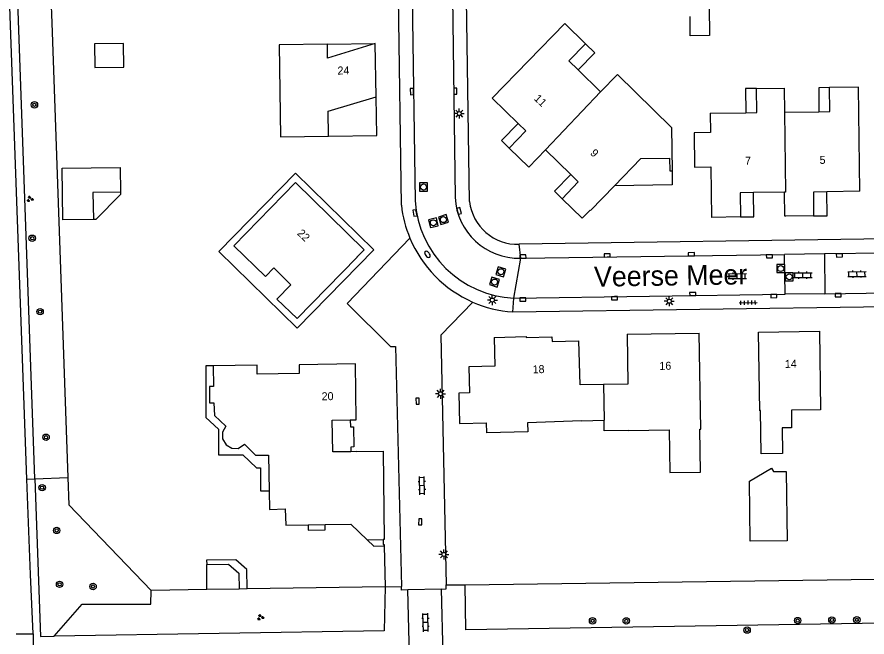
# Model space of a CAD drawing. Extents: x 128999 to 131010, y 395498 to 399007.
# Drawn here: x 130797.9 to 130904, y 395695.7 to 395773.2 of the extents above; entities that cross this region are included whole.
import ezdxf

# ---------------------------------------------------------------- set-up
doc = ezdxf.new("R2010")
doc.units = 0
for name, color, linetype in [('gg-afsc-erfafscheiding', 7, 'Continuous'), ('gg-afsc-hekwerk', 7, 'Continuous'), ('gg-afsc-muur', 7, 'Continuous'), ('gg-anno-huisnummerreeks BGT', 7, 'Continuous'), ('gg-anno-openbare ruimte label', 7, 'Continuous'), ('gg-bbg-bijgebouw', 7, 'Continuous'), ('gg-bbg-gedigitaliseerde bebouwing', 7, 'Continuous'), ('gg-bbg-gedigitaliseerde bijgebouw', 7, 'Continuous'), ('gg-bbg-hoofdgebouw', 7, 'Continuous'), ('gg-bbg-luifel en loopbrug', 7, 'Continuous'), ('gg-bbg-onder overbouw', 7, 'Continuous'), ('gg-bbg-pand overbouw', 7, 'Continuous'), ('gg-bbg-tussenscheiding', 7, 'Continuous'), ('gg-knt-verharding', 7, 'Continuous'), ('gt-grn-groengrens', 7, 'Continuous'), ('gt-grn-vlakafsluiter', 7, 'Continuous'), ('gt-grn-weggrens', 7, 'Continuous'), ('gt-symb-boom', 7, 'Continuous'), ('gt-symb-brandkraan', 7, 'Continuous'), ('gt-symb-groenvak', 7, 'Continuous'), ('gt-symb-klinker verharding', 7, 'Continuous'), ('gt-symb-kolk', 7, 'Continuous'), ('gt-symb-lichtmast', 7, 'Continuous'), ('gt-symb-rioolschacht', 7, 'Continuous'), ('gt-symb-tegel verharding', 7, 'Continuous')]:
    doc.layers.add(name, color=color, linetype=linetype)

# ---------------------------------------------------------------- blocks, each defined once
blk = doc.blocks.new('gt0-RS')
at = {"layer": 'gt-symb-rioolschacht'}
blk.add_lwpolyline([(-0.5, -0.5), (0.5, -0.5), (0.5, 0.5), (-0.5, 0.5)], close=True, dxfattribs=at)
blk.add_circle((0, 0), 0.375, dxfattribs=at)
blk = doc.blocks.new('gt0-KOLK')
at = {"layer": 'gt-symb-kolk'}
blk.add_lwpolyline([(0, 0), (0.38, 0), (0.38, 0.4), (-0.38, 0.4), (-0.38, 0), (0, 0)], dxfattribs=at)
blk = doc.blocks.new('gt0-KL1')
at = {"layer": 'gt-symb-klinker verharding'}
for p, q in [((-1.15, 0.3), (1.15, 0.3)), ((-1, -0.3), (-1, 0.3)), ((-0.5, 0.3), (-0.5, 0.45)), ((0, -0.3), (0, 0.3)), ((0.5, 0.3), (0.5, 0.45)), ((1, -0.3), (1, 0.3)), ((-1.15, -0.3), (1.15, -0.3)), ((-0.5, -0.45), (-0.5, -0.3)), ((0.5, -0.45), (0.5, -0.3))]:
    blk.add_line(p, q, dxfattribs=at)
blk = doc.blocks.new('gt0-BR')
at = {"layer": 'gt-symb-brandkraan'}
for centre, radius, start, end in [((-0.24, 0), 0.206, 107.5669, 252.4331), ((0.6, -2.66), 3, 106.892, 107.5669), ((0, -0.69), 0.938, 73.108, 106.892), ((-0.6, -2.66), 3, 72.4331, 73.108), ((0.24, 0), 0.206, 287.567, 72.4331), ((0.6, 2.66), 3, 252.4331, 253.108), ((0, 0.69), 0.938, 253.108, 286.8921), ((-0.6, 2.66), 3, 286.8921, 287.567)]:
    blk.add_arc(centre, radius, start, end, dxfattribs=at)
blk = doc.blocks.new('gt0-LMAST')
at = {"layer": 'gt-symb-lichtmast'}
for p, q in [((-0.18, 0.17), (-0.45, 0.44)), ((-0.01, 0.25), (-0.01, 0.62)), ((0.17, 0.17), (0.44, 0.44)), ((-0.26, 0), (-0.63, 0)), ((-0.18, -0.18), (-0.45, -0.45)), ((-0.01, -0.25), (-0.01, -0.63)), ((0.44, -0.45), (0.17, -0.18)), ((0.24, 0), (0.62, 0))]:
    blk.add_line(p, q, dxfattribs=at)
blk.add_circle((-0.01, 0), 0.25, dxfattribs=at)
blk = doc.blocks.new('gt0-TEG1')
at = {"layer": 'gt-symb-tegel verharding'}
for p, q in [((-1.12, 0), (1.12, 0)), ((-0.9, -0.25), (-0.9, 0.25)), ((-0.45, -0.25), (-0.45, 0.25)), ((0, -0.25), (0, 0.25)), ((0.45, -0.25), (0.45, 0.25)), ((0.9, -0.25), (0.9, 0.25))]:
    blk.add_line(p, q, dxfattribs=at)
blk = doc.blocks.new('gt0-BOOM')
at = {"layer": 'gt-symb-boom'}
for radius in [0.4, 0.2]:
    blk.add_circle((0, 0), radius, dxfattribs=at)
blk = doc.blocks.new('gt0-GRVAK')
at = {"layer": 'gt-symb-groenvak'}
for p, q in [((-0.11, 0.19), (-0.23, 0.24)), ((-0.18, 0.15), (0.09, 0.15)), ((-0.09, 0.21), (-0.16, 0.32)), ((-0.05, 0.21), (-0.05, 0.39)), ((0, 0.21), (0.06, 0.32)), ((0.01, 0.19), (0.13, 0.24)), ((0.26, -0.05), (0.2, 0.06)), ((0.31, -0.05), (0.31, 0.13)), ((0.35, -0.05), (0.41, 0.06)), ((-0.24, -0.23), (-0.36, -0.18)), ((-0.32, -0.26), (-0.05, -0.26)), ((-0.23, -0.21), (-0.29, -0.1)), ((-0.18, -0.2), (-0.18, -0.02)), ((-0.14, -0.21), (-0.07, -0.1)), ((-0.12, -0.23), (0, -0.18)), ((0.24, -0.07), (0.12, -0.02)), ((0.17, -0.11), (0.44, -0.11)), ((0.37, -0.07), (0.49, -0.02))]:
    blk.add_line(p, q, dxfattribs=at)

msp = doc.modelspace()

# ---------------------------------------------------------------- linework, layer by layer
at = {"layer": 'gg-afsc-erfafscheiding'}
for p, q in [((130802.21, 395772.43), (130804.21, 395715.6)), ((130804.21, 395715.6), (130804.33, 395712.2)), ((130814.6, 395701.51), (130804.33, 395712.2)), ((130821.58, 395701.61), (130814.6, 395701.51))]:
    msp.add_line(p, q, dxfattribs=at)
at = {"layer": 'gg-afsc-hekwerk'}
msp.add_line((130800.51, 395824.79), (130802.21, 395772.43), dxfattribs=at)
at = {"layer": 'gg-afsc-muur'}
for p, q in [((130843.72, 395707.06), (130843.84, 395701.97)), ((130843.84, 395701.97), (130826.59, 395701.69))]:
    msp.add_line(p, q, dxfattribs=at)
at = {"layer": 'gg-bbg-bijgebouw'}
for p, q in [((130821.58, 395701.61), (130821.55, 395704.73)), ((130825.59, 395701.67), (130821.58, 395701.61))]:
    msp.add_line(p, q, dxfattribs=at)
at = {"layer": 'gg-bbg-gedigitaliseerde bebouwing'}
for p, q in [((130857.22, 395762.99), (130866.28, 395772.32)), ((130866.28, 395772.32), (130868.86, 395769.81)), ((130867.93, 395766.55), (130870.75, 395763.81)), ((130884.42, 395761.13), (130888.89, 395761.19)), ((130884.42, 395761.13), (130884.45, 395758.72)), ((130893.72, 395761.27), (130898.01, 395761.32)), ((130863.85, 395756.54), (130861.79, 395754.37)), ((130884.51, 395754.41), (130884.59, 395748.11)), ((130833.1, 395729.71), (130833.1, 395728.59)), ((130868.35, 395722.71), (130871.18, 395722.76)), ((130831.42, 395709.67), (130834.21, 395709.71)), ((130834.21, 395709.71), (130836.33, 395709.75)), ((130841.59, 395707.83), (130843.6, 395707.86))]:
    msp.add_line(p, q, dxfattribs=at)
for points in [[(130836.62, 395769.76), (130830.59, 395769.68), (130830.78, 395758.18), (130836.78, 395758.26)], [(130868.86, 395769.81), (130866.78, 395767.66), (130867.93, 395766.55)], [(130870.75, 395763.81), (130872.84, 395765.96), (130879.59, 395759.36), (130879.67, 395753.95)], [(130888.89, 395761.19), (130890.26, 395761.21), (130890.22, 395764.21)], [(130890.22, 395764.21), (130893.68, 395764.26), (130893.72, 395761.27)], [(130898.01, 395761.32), (130899.38, 395761.34), (130899.35, 395764.33)], [(130903.13, 395751.39), (130902.94, 395764.37), (130899.35, 395764.33)], [(130884.45, 395758.72), (130882.43, 395758.69), (130882.48, 395754.38), (130884.51, 395754.41)], [(130832.65, 395752.46), (130824.95, 395744.57), (130828.89, 395740.73)], [(130828.89, 395740.73), (130829.92, 395741.79), (130832.07, 395739.69), (130830.33, 395737.91)], [(130874.24, 395721.5), (130879.29, 395721.58), (130879.38, 395716.24), (130883.21, 395716.3), (130883.14, 395721.65), (130883.25, 395721.65), (130883.07, 395733.64)], [(130898.07, 395733.88), (130898.21, 395724.08), (130894.57, 395724.01), (130894.6, 395721.82), (130893.41, 395721.8), (130893.47, 395718.61), (130890.78, 395718.57), (130890.71, 395723.97), (130890.61, 395723.96), (130890.47, 395733.76)], [(130822.35, 395729.57), (130822.41, 395726.98), (130821.9, 395726.97), (130821.89, 395724.94), (130822.45, 395724.96), (130822.52, 395723.35), (130823.93, 395722.02), (130823.51, 395721.27), (130823.54, 395720.44), (130823.97, 395719.71), (130824.7, 395719.3), (130825.5, 395719.25), (130826.26, 395719.76), (130827.65, 395718.4), (130829.27, 395718.42), (130829.34, 395713.94)], [(130833.1, 395728.59), (130827.85, 395728.51), (130827.84, 395729.65), (130822.35, 395729.57)], [(130868.35, 395722.71), (130861.63, 395722.44), (130861.66, 395721.31)], [(130874.24, 395721.5), (130871.2, 395721.45), (130871.18, 395722.76)], [(130829.34, 395713.94), (130829.38, 395711.63), (130831.37, 395711.68), (130831.42, 395709.67)], [(130836.33, 395709.75), (130839.56, 395709.8), (130841.59, 395707.83)]]:
    msp.add_lwpolyline(points, dxfattribs=at)
at = {"layer": 'gg-bbg-gedigitaliseerde bijgebouw'}
for points in [[(130807.54, 395769.79), (130807.59, 395766.85), (130811.21, 395766.9), (130811.16, 395769.85), (130807.54, 395769.79)], [(130803.5, 395754.25), (130810.74, 395754.36), (130810.79, 395751.28)], [(130807.4, 395747.85), (130803.6, 395747.79), (130803.5, 395754.25)], [(130810.79, 395751.28), (130807.35, 395751.23), (130807.4, 395747.85)], [(130892.07, 395716.78), (130892.32, 395716.35), (130893.92, 395716.38), (130894.04, 395707.71), (130889.44, 395707.65), (130889.34, 395715.14), (130892.07, 395716.78)], [(130821.55, 395704.73), (130824.26, 395704.8), (130825.56, 395703.67), (130825.59, 395701.67)]]:
    msp.add_lwpolyline(points, dxfattribs=at)
at = {"layer": 'gg-bbg-hoofdgebouw'}
for p, q in [((130842.71, 395763.19), (130842.61, 395769.85)), ((130860.46, 395759.84), (130857.22, 395762.99)), ((130861.79, 395754.37), (130859.31, 395756.77)), ((130867.02, 395753.47), (130863.85, 395756.54)), ((130893.71, 395751.25), (130889.83, 395751.21)), ((130903.13, 395751.39), (130898.98, 395751.3)), ((130888.2, 395748.18), (130884.59, 395748.11)), ((130897.35, 395748.29), (130893.89, 395748.25)), ((130830.33, 395737.91), (130832.84, 395735.46)), ((130874.07, 395733.51), (130883.07, 395733.64)), ((130890.47, 395733.76), (130898.07, 395733.88)), ((130857.45, 395733.1), (130857.54, 395729.51)), ((130840.12, 395729.82), (130833.1, 395729.71)), ((130840.29, 395718.85), (130839.56, 395718.84))]:
    msp.add_line(p, q, dxfattribs=at)
for points in [[(130836.78, 395758.26), (130836.74, 395761.38), (130842.71, 395763.19)], [(130859.31, 395756.77), (130861.4, 395758.92), (130860.46, 395759.84)], [(130872.47, 395752.06), (130875.78, 395755.46), (130879.35, 395755.51), (130879.38, 395753.94), (130879.67, 395753.95)], [(130865.93, 395750.45), (130867.96, 395752.55), (130867.02, 395753.47)], [(130832.65, 395752.46), (130841.23, 395744.08), (130840.3, 395743.13), (130840.31, 395743.11), (130832.84, 395735.46)], [(130865.93, 395750.45), (130868.44, 395748.01), (130869.44, 395749.03), (130869.49, 395748.99), (130872.47, 395752.06)], [(130889.83, 395751.21), (130888.16, 395751.19), (130888.2, 395748.18)], [(130893.89, 395748.25), (130893.74, 395748.25), (130893.71, 395751.25)], [(130898.98, 395751.3), (130897.32, 395751.27), (130897.35, 395748.29)], [(130857.45, 395733.1), (130861.44, 395733.23), (130861.45, 395733.09), (130864.67, 395733.2), (130864.69, 395732.6), (130868.01, 395732.71)], [(130874.07, 395733.51), (130874.16, 395727.27), (130871.12, 395727.23)], [(130871.12, 395727.23), (130868.2, 395727.2), (130868.01, 395732.71)], [(130839.48, 395722.82), (130840.23, 395722.83), (130840.12, 395729.82)], [(130857.54, 395729.51), (130854.29, 395729.44), (130854.37, 395726.19), (130853.03, 395726.16)], [(130853.03, 395726.16), (130853.12, 395722.35), (130856.51, 395722.43)], [(130839.56, 395718.84), (130837.29, 395718.81), (130837.23, 395722.79), (130839.48, 395722.82)], [(130861.66, 395721.31), (130856.54, 395721.18), (130856.51, 395722.43)], [(130840.29, 395718.85), (130843.57, 395718.9), (130843.7, 395707.86), (130843.6, 395707.86)]]:
    msp.add_lwpolyline(points, dxfattribs=at)
at = {"layer": 'gg-bbg-luifel en loopbrug'}
msp.add_line((130826.59, 395701.69), (130825.59, 395701.67), dxfattribs=at)
for points in [[(130884.3, 395774.47), (130884.34, 395770.82), (130881.94, 395770.79), (130881.91, 395773.23)], [(130868.86, 395769.81), (130870.01, 395768.69), (130867.93, 395766.55)], [(130890.22, 395764.21), (130888.85, 395764.2), (130888.89, 395761.19)], [(130899.35, 395764.33), (130897.98, 395764.31), (130898.01, 395761.32)], [(130836.78, 395758.26), (130842.78, 395758.35), (130842.71, 395763.19)], [(130859.31, 395756.77), (130858.37, 395757.7), (130860.46, 395759.84)], [(130823.06, 395743.85), (130832.84, 395734.29), (130842.41, 395744.08), (130832.63, 395753.64), (130823.06, 395743.85)], [(130865.93, 395750.45), (130864.98, 395751.38), (130867.02, 395753.47)], [(130879.67, 395753.95), (130879.7, 395752.17), (130872.47, 395752.06)], [(130810.79, 395751.28), (130810.79, 395750.98), (130807.7, 395747.86), (130807.4, 395747.85)], [(130888.2, 395748.18), (130889.86, 395748.2), (130889.83, 395751.21)], [(130897.35, 395748.29), (130899.02, 395748.31), (130898.98, 395751.3)], [(130822.35, 395729.57), (130821.46, 395729.57), (130821.46, 395723.13), (130823.04, 395721.64), (130823.04, 395718.45), (130826.05, 395718.45), (130827.77, 395716.82), (130828.27, 395716.82), (130828.27, 395713.94), (130829.34, 395713.94)], [(130839.48, 395722.82), (130839.5, 395721.93), (130839.9, 395721.93), (130839.94, 395719.43), (130839.55, 395719.42), (130839.56, 395718.84)], [(130834.21, 395709.71), (130834.22, 395709.04), (130836.34, 395709.07), (130836.33, 395709.75)], [(130841.59, 395707.83), (130842.41, 395707.05), (130843.72, 395707.06)], [(130843.6, 395707.86), (130843.61, 395707.25), (130843.71, 395707.25), (130843.72, 395707.06)], [(130826.59, 395701.69), (130826.55, 395704.14), (130825.18, 395705.32), (130821.54, 395705.27), (130821.55, 395704.73)]]:
    msp.add_lwpolyline(points, dxfattribs=at)
at = {"layer": 'gg-bbg-onder overbouw'}
msp.add_lwpolyline([(130842.61, 395769.85), (130836.64, 395768.02), (130836.62, 395769.76)], dxfattribs=at)
at = {"layer": 'gg-bbg-pand overbouw'}
msp.add_line((130836.62, 395769.76), (130842.61, 395769.85), dxfattribs=at)
at = {"layer": 'gg-bbg-tussenscheiding'}
for p, q in [((130870.75, 395763.81), (130863.85, 395756.54)), ((130871.12, 395727.23), (130871.18, 395722.76))]:
    msp.add_line(p, q, dxfattribs=at)
msp.add_lwpolyline([(130893.72, 395761.27), (130893.85, 395751.25), (130893.71, 395751.25)], dxfattribs=at)
at = {"layer": 'gg-knt-verharding'}
for p, q in [((130799.11, 395715.42), (130792.95, 395886.49)), ((130852, 395793.69), (130852.58, 395750.61)), ((130846.96, 395793.53), (130847.57, 395750.19)), ((130928.3, 395745.77), (130860.57, 395744.75)), ((130927.72, 395743.93), (130898.71, 395743.54)), ((130860.77, 395743.03), (130893.73, 395743.47)), ((130898.71, 395743.54), (130893.73, 395743.47)), ((130893.81, 395738.5), (130893.73, 395743.47)), ((130898.71, 395743.54), (130898.73, 395738.57)), ((130859.91, 395738.03), (130893.81, 395738.5)), ((130898.73, 395738.57), (130893.81, 395738.5)), ((130898.73, 395738.57), (130927.16, 395738.97)), ((130926.92, 395737.24), (130859.78, 395736.29)), ((130799.54, 395703.48), (130799.11, 395715.42)), ((130799.88, 395696.09), (130799.54, 395703.48)), ((130850.88, 395701.68), (130846.66, 395701.56)), ((130846.88, 395693.37), (130846.66, 395701.56)), ((130851.1, 395693.41), (130850.88, 395701.68)), ((130797.75, 395696.09), (130799.88, 395696.09)), ((130799.88, 395696.09), (130799.95, 395692.82))]:
    msp.add_line(p, q, dxfattribs=at)
for points in [[(130845.87, 395749.62), (130845.12, 395801.5), (130844.38, 395857.63)], [(130854.38, 395750.1), (130853.62, 395800.73), (130852.88, 395857.84)], [(130846.94, 395745.52), (130839.1, 395737.36), (130844.52, 395731.97), (130845.11, 395731.97), (130845.88, 395702)], [(130854.77, 395737.54), (130850.8, 395733.38), (130851.46, 395702.19)], [(130846.66, 395701.56), (130845.89, 395701.54), (130845.88, 395702)], [(130850.88, 395701.68), (130851.47, 395701.69), (130851.46, 395702.19)]]:
    msp.add_lwpolyline(points, dxfattribs=at)
for centre, radius, start, end in [((130860.53, 395751), 12.99, 183.5836, 267.286), ((130860.51, 395750.96), 7.94, 182.5215, 271.848), ((130860.83, 395751.33), 15.06, 186.5107, 202.6833), ((130860.38, 395750.79), 6.04, 186.5526, 271.771), ((130860.84, 395751.33), 15.07, 202.6742, 246.2171), ((130860.84, 395751.33), 15.07, 246.2162, 265.9321)]:
    msp.add_arc(centre, radius, start, end, dxfattribs=at)
at = {"layer": 'gt-grn-groengrens'}
for p, q in [((130799.11, 395715.42), (130800.1, 395715.45)), ((130800.1, 395715.45), (130804.21, 395715.6))]:
    msp.add_line(p, q, dxfattribs=at)
for points in [[(130800.1, 395715.45), (130793.95, 395886.12), (130793.99, 395888.96), (130794.71, 395892.91), (130796.85, 395897.52), (130799.92, 395901.1), (130803.59, 395902.78), (130807.67, 395902.98)], [(130800.1, 395715.45), (130800.8, 395695.75), (130802.49, 395695.81)], [(130843.84, 395701.97), (130843.73, 395696.44), (130802.49, 395695.81)], [(130802.49, 395695.81), (130806.01, 395699.79), (130814.57, 395699.79), (130814.6, 395701.51)], [(130986.77, 395698.72), (130853.93, 395696.6), (130853.81, 395702.22)]]:
    msp.add_lwpolyline(points, dxfattribs=at)
at = {"layer": 'gt-grn-vlakafsluiter'}
for p, q in [((130843.84, 395701.97), (130845.88, 395702)), ((130851.46, 395702.19), (130853.81, 395702.22))]:
    msp.add_line(p, q, dxfattribs=at)
msp.add_lwpolyline([(130853.81, 395702.22), (130980.39, 395703.95), (130986.9, 395718.19)], dxfattribs=at)
at = {"layer": 'gt-grn-weggrens'}
for p, q in [((130860.77, 395743.03), (130860.57, 395744.75)), ((130859.91, 395738.03), (130860.77, 395743.03)), ((130859.78, 395736.29), (130859.91, 395738.03))]:
    msp.add_line(p, q, dxfattribs=at)

# ---------------------------------------------------------------- block references
at = {"layer": 'gt-symb-boom'}
for p in [(130800.04, 395762.18), (130799.76, 395745.51), (130800.75, 395736.34), (130801.49, 395720.65), (130801, 395714.34), (130802.82, 395709), (130803.18, 395702.27), (130807.36, 395702), (130895.36, 395697.74), (130899.63, 395697.81), (130902.74, 395697.83), (130869.74, 395697.71), (130873.95, 395697.7), (130889.04, 395696.55)]:
    msp.add_blockref('gt0-BOOM', p, dxfattribs=at)
at = {"layer": 'gt-symb-brandkraan', "rotation": 128.50778297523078}
msp.add_blockref('gt0-BR', (130849.12, 395743.5), dxfattribs=at)
at = {"layer": 'gt-symb-groenvak'}
for p in [(130799.48, 395750.4), (130828.26, 395698.15)]:
    msp.add_blockref('gt0-GRVAK', p, dxfattribs=at)
at = {"layer": 'gt-symb-klinker verharding'}
for p, rotation in [((130887.8, 395740.78), 0.8020885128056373), ((130896.01, 395740.89), -0.11459140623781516), ((130902.76, 395741.03), 0.8593722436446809), ((130848.44, 395714.59), 91.0884888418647), ((130848.88, 395697.5), 91.5466102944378)]:
    msp.add_blockref('gt0-KL1', p, dxfattribs=dict(at, rotation=rotation))
at = {"layer": 'gt-symb-kolk'}
for p, rotation in [((130847.38, 395763.83), 90.74480317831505), ((130852.4, 395763.88), -89.25519682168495), ((130847.75, 395748.7), 100.5457343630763), ((130852.87, 395748.87), -75.10181274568), ((130861.05, 395743.03), 0.40106390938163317), ((130871.57, 395743.17), 0.9166542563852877), ((130882.08, 395743.31), 0.9166542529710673), ((130891.82, 395743.45), -179.14062775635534), ((130900.56, 395743.56), -179.14062775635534), ((130882.25, 395738.34), 0.8020885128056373), ((130892.37, 395738.48), -179.1979114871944), ((130900.4, 395738.59), -179.1979114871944), ((130861.02, 395738.05), -179.14062775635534), ((130872.47, 395738.21), -179.14062775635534), ((130848.09, 395725.15), 90.57293869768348), ((130848.42, 395710.08), 89.36977184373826)]:
    msp.add_blockref('gt0-KOLK', p, dxfattribs=dict(at, rotation=rotation))
at = {"layer": 'gt-symb-lichtmast'}
for p in [(130853.1, 395761.09), (130857.23, 395737.79), (130879.33, 395737.64), (130850.77, 395726.07), (130851.19, 395706.01)]:
    msp.add_blockref('gt0-LMAST', p, dxfattribs=at)
at = {"layer": 'gt-symb-rioolschacht'}
for p in [(130848.63, 395751.91), (130893.24, 395741.72), (130894.3, 395740.69)]:
    msp.add_blockref('gt0-RS', p, dxfattribs=at)
for p, rotation in [((130849.86, 395747.44), 13.174926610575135), ((130851.11, 395747.83), 17.039535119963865), ((130858.29, 395741.32), -15.843082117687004), ((130857.5, 395740.03), -18.181268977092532)]:
    msp.add_blockref('gt0-RS', p, dxfattribs=dict(at, rotation=rotation))
at = {"layer": 'gt-symb-tegel verharding', "rotation": 0.8593722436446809}
msp.add_blockref('gt0-TEG1', (130889.17, 395737.46), dxfattribs=at)

# ---------------------------------------------------------------- texts
at = {"layer": 'gg-anno-huisnummerreeks BGT'}
for s, rotation, p in [('24', 0.9, (130837.89, 395765.96)), ('11', 315.8, (130862.35, 395762.88)), ('9', 315.8, (130869.37, 395756.06)), ('7', 0.7, (130888.79, 395754.69)), ('5', 1.1, (130898.1, 395754.79)), ('22', 315.7, (130832.78, 395746.04)), ('16', 0.9, (130878.09, 395729.06)), ('14', 0.9, (130893.76, 395729.31)), ('18', 1.9, (130862.27, 395728.62)), ('20', 0.9, (130835.91, 395725.26))]:
    msp.add_text(s, height=1, rotation=rotation, dxfattribs=at).set_placement(p)
at = {"layer": 'gg-anno-openbare ruimte label'}
msp.add_text('Veerse Meer', height=2.5, rotation=0.9, dxfattribs=at).set_placement((130869.94, 395739.45))

doc.saveas('drawing.dxf')
